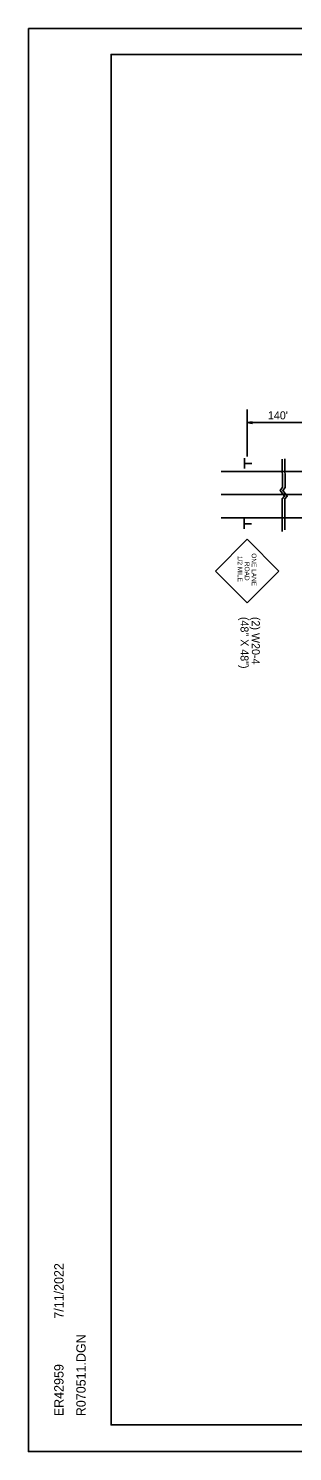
# Model space of a CAD drawing. Extents: x 1398460 to 1408037, y 380768 to 383968.
# Drawn here: x 1398999 to 1399197, y 381834 to 382901 of the extents above; entities that cross this region are included whole.
import ezdxf

# ---------------------------------------------------------------- set-up
doc = ezdxf.new("R2010")
doc.units = 0
for name, color, linetype in [('Default', 7, 'Continuous'), ('R_Border', 7, 'Continuous'), ('R_No Plot', 7, 'Continuous')]:
    doc.layers.add(name, color=color, linetype=linetype)

msp = doc.modelspace()

# ---------------------------------------------------------------- linework, layer by layer
at = {"layer": 'Default'}
for p, q in [((1399163.1, 382615.3), (1399163.1, 382580.1)), ((1399163.1, 382615.3), (1399163.1, 382580)), ((1399166.8, 382606), (1399163.1, 382605.5)), ((1399166.9, 382606), (1399163.1, 382605.5)), ((1399166.8, 382604.9), (1399163.1, 382605.5)), ((1399166.9, 382604.9), (1399163.1, 382605.5)), ((1399163.1, 382605.5), (1399215.3, 382605.5)), ((1399166.8, 382605.9), (1399163.7, 382605.5)), ((1399166.8, 382605), (1399163.7, 382605.5)), ((1399166.9, 382605.9), (1399163.8, 382605.5)), ((1399166.9, 382605), (1399163.8, 382605.5)), ((1399166.8, 382605.9), (1399164.4, 382605.5)), ((1399166.9, 382605.8), (1399164.4, 382605.5)), ((1399166.8, 382605.1), (1399164.4, 382605.5)), ((1399166.9, 382605.1), (1399164.4, 382605.5)), ((1399166.8, 382605.8), (1399165, 382605.5)), ((1399166.9, 382605.7), (1399165, 382605.5)), ((1399166.8, 382605.2), (1399165, 382605.5)), ((1399166.9, 382605.2), (1399165, 382605.5)), ((1399166.8, 382605.7), (1399165.6, 382605.5)), ((1399166.8, 382605.3), (1399165.6, 382605.5)), ((1399166.9, 382605.6), (1399165.7, 382605.5)), ((1399166.9, 382605.3), (1399165.7, 382605.5)), ((1399166.8, 382605.6), (1399166.3, 382605.5)), ((1399166.8, 382605.4), (1399166.3, 382605.5)), ((1399166.9, 382605.5), (1399166.3, 382605.5)), ((1399166.9, 382605.4), (1399166.3, 382605.5)), ((1399166.8, 382604.9), (1399166.8, 382606)), ((1399166.9, 382604.9), (1399166.9, 382606)), ((1399161, 382571), (1399161, 382578.9)), ((1399143.6, 382568.9), (1399212.4, 382568.9)), ((1399161.1, 382574.9), (1399166.5, 382574.9)), ((1399143.6, 382551.5), (1399213.1, 382551.5)), ((1399143.6, 382534.1), (1399212.4, 382534.1)), ((1399160.9, 382525.9), (1399160.9, 382533.7)), ((1399161, 382529.7), (1399166.4, 382529.7)), ((1399139.2, 382494.2), (1399163.1, 382518.1)), ((1399187, 382494.2), (1399163.1, 382518.1)), ((1399163.1, 382470.3), (1399139.2, 382494.2)), ((1399163.1, 382470.3), (1399187, 382494.2))]:
    msp.add_line(p, q, dxfattribs=at)
for points in [[(1399189.3, 382578.1), (1399189.6, 382557), (1399188, 382554.6), (1399191.2, 382550.3), (1399189.5, 382548.3), (1399189.5, 382523.8)], [(1399191.3, 382578.2), (1399191.6, 382556.9), (1399190, 382554.5), (1399193.2, 382550.2), (1399191.5, 382548.2), (1399191.5, 382525.2)]]:
    msp.add_lwpolyline(points, dxfattribs=at)
at = {"layer": 'R_Border'}
for p, q in [((1399060.9, 382881.4), (1400641.8, 382881.4)), ((1399060.9, 381854.1), (1399060.9, 382881.4)), ((1399060.9, 381854.1), (1399060.9, 381854.1)), ((1400641.8, 381854.1), (1399060.9, 381854.1))]:
    msp.add_line(p, q, dxfattribs=at)
at = {"layer": 'R_No Plot'}
for p, q in [((1398998.9, 382900.9), (1400665.5, 382900.9)), ((1398998.9, 381834.2), (1400665.5, 381834.2))]:
    msp.add_line(p, q, dxfattribs=at)
for points in [[(1398998.8, 382900.9), (1400665.5, 382900.9), (1400665.5, 381834.2), (1398998.8, 381834.2)], [(1400230.5, 382881.4), (1400328.6, 382881.4), (1400328.6, 382832), (1400409.1, 382832), (1400525.1, 382832), (1400525.1, 382710.4), (1400641.8, 382710.4), (1400641.8, 381854.1), (1399060.9, 381854.1), (1399060.9, 382881.4)]]:
    msp.add_lwpolyline(points, close=True, dxfattribs=at)

# ---------------------------------------------------------------- texts
at = {"layer": 'Default'}
msp.add_text("140'", height=6, dxfattribs=at).set_placement((1399178.7, 382607.9))
for s, height, rotation, p in [('1/2 MILE', 3.52, 270.0006, (1399156, 382505.5)), ('ONE LANE', 3.52, 270.0004, (1399166.5, 382507.5)), ('ROAD', 3.52, 270, (1399161.3, 382501.1)), ('(48" X 48")', 6, 270, (1399158.1, 382459.8)), ('(2) W20-4', 6, 270, (1399166.6, 382459.8))]:
    msp.add_text(s, height=height, rotation=rotation, dxfattribs=at).set_placement(p)
at = {"layer": 'R_Border'}
for s, p in [('7/11/2022', (1399025.2, 381933.8)), ('R070511.DGN', (1399041.8, 381860.7)), ('ER42959', (1399025.2, 381860.7))]:
    msp.add_text(s, height=7, rotation=90, dxfattribs=at).set_placement(p)

doc.saveas('drawing.dxf')
